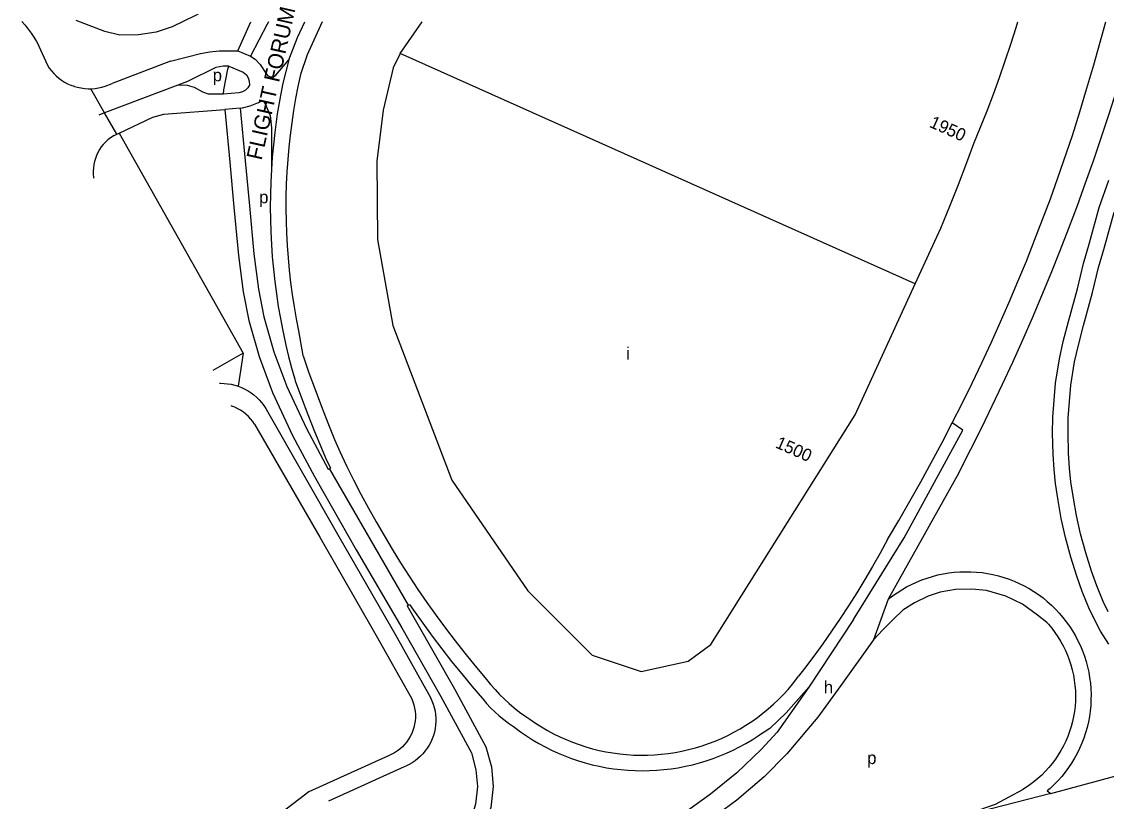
# Model space of a CAD drawing. Extents: x 154765 to 156627, y 383996 to 386132.
# Drawn here: x 155637.8 to 155986.3, y 384249.3 to 384500 of the extents above; entities that cross this region are included whole.
import ezdxf

# ---------------------------------------------------------------- set-up
doc = ezdxf.new("R2010")
doc.units = 0
for name, color, linetype in [('BLT_Basislijn', 7, 'Continuous'), ('BLT_Bebouwing', 7, 'Continuous'), ('BLT_Centroide', 7, 'Continuous'), ('BLT_Huisnummer', 7, 'Continuous'), ('BLT_Huisnummer_reeks', 7, 'Continuous'), ('BLT_Onderverdeling_panden', 7, 'Continuous'), ('BLT_Straatnaam', 7, 'Continuous'), ('BLT_Vlakafsluiter', 7, 'Continuous')]:
    doc.layers.add(name, color=color, linetype=linetype)

msp = doc.modelspace()

# ---------------------------------------------------------------- linework, layer by layer
at = {"layer": 'BLT_Basislijn'}
for p, q in [((155982.27, 384486.09), (155986.13, 384499.98)), ((155643.35, 384492.1), (155646.06, 384486.01)), ((155707.25, 384490.59), (155711.28, 384488.93)), ((155685.59, 384487.29), (155666.85, 384480.09)), ((155980.06, 384478.55), (155982.27, 384486.09)), ((155977.77, 384471.03), (155980.06, 384478.55)), ((155664.46, 384470.64), (155659.99, 384478.42)), ((155708.04, 384472.13), (155703.05, 384471.71)), ((155668.4, 384463.77), (155664.46, 384470.64)), ((155975.44, 384463.36), (155977.77, 384471.03)), ((155667.56, 384463.42), (155668.4, 384463.77)), ((155668.4, 384463.77), (155669.14, 384464.08)), ((155708.93, 384393.37), (155699.2, 384387.82)), ((155716.76, 384374.68), (155739.69, 384334.47)), ((155712.63, 384370.54), (155733.64, 384334.24)), ((155736.23, 384356.1), (155736.99, 384356.46)), ((155736.61, 384356.28), (155762, 384312.37)), ((155938.74, 384354.75), (155916.19, 384314.26)), ((155733.64, 384334.24), (155751.74, 384302.65)), ((155739.69, 384334.47), (155757.87, 384302.8)), ((155761.61, 384312.12), (155762.39, 384312.61)), ((155905.08, 384307.74), (155890.71, 384285.95)), ((155751.74, 384302.65), (155762.65, 384283.24)), ((155757.87, 384302.8), (155769.16, 384282.63)), ((155890.71, 384285.95), (155880.57, 384271.55)), ((155968.5, 384251.86), (156049.38, 384273.6)), ((155760.67, 384260.41), (155736.36, 384249.3)), ((155967.32, 384252.64), (155968.5, 384251.86))]:
    msp.add_line(p, q, dxfattribs=at)
for points in [[(155734.71, 384537.35), (155704.01, 384507.98), (155693.62, 384502.02), (155686.13, 384498.37), (155680.99, 384496.61), (155675.34, 384495.78), (155669.38, 384495.69), (155664.51, 384496.83), (155655.33, 384500.35)], [(155637.8, 384500), (155638.88, 384498.82), (155639.9, 384497.59), (155640.85, 384496.3), (155641.74, 384494.98), (155642.55, 384493.61), (155643.3, 384492.2), (155643.35, 384492.1)], [(155707.25, 384490.59), (155711.4, 384499.98)], [(155717.15, 384499.98), (155716.64, 384499.15)], [(155734.36, 384499.98), (155729.52, 384489.29), (155727.39, 384483.04), (155726.56, 384479.17), (155725.82, 384475.28), (155725.15, 384471.38), (155724.56, 384467.46), (155724.06, 384463.54), (155723.63, 384459.6), (155723.28, 384455.66), (155723.01, 384451.71), (155722.82, 384447.75), (155722.71, 384443.8), (155722.68, 384439.84), (155722.73, 384435.88), (155722.86, 384431.93), (155723.07, 384427.97), (155723.37, 384424.03), (155723.74, 384420.08), (155724.18, 384416.15), (155724.71, 384412.23), (155725.32, 384408.32), (155726.01, 384404.42), (155726.76, 384400.6)], [(155723.64, 384487.72), (155726.46, 384494.94), (155728.74, 384499.98)], [(155716.64, 384499.15), (155711.28, 384488.93)], [(155685.59, 384487.29), (155695.27, 384489.76), (155698.22, 384490.32), (155701.2, 384490.61), (155707.25, 384490.59)], [(155711.28, 384488.93), (155712.79, 384487.96), (155714.46, 384486.26), (155716.25, 384483.38), (155716.86, 384482.61), (155717.71, 384482.23), (155718.67, 384482.25), (155719.5, 384482.77), (155723.64, 384487.72)], [(155646.06, 384486.01), (155646.67, 384485.08), (155647.34, 384484.18), (155648.08, 384483.34), (155648.87, 384482.56), (155649.72, 384481.83), (155650.62, 384481.17), (155651.57, 384480.57), (155652.55, 384480.04), (155653.57, 384479.58), (155654.62, 384479.2), (155654.76, 384479.16)], [(155704.32, 384485.64), (155702.56, 384485.64), (155700.22, 384485.22), (155691.03, 384480.73), (155687.97, 384479.57)], [(155702.64, 384476.69), (155702.72, 384478.11), (155704.07, 384484.72), (155704.32, 384485.64)], [(155704.32, 384485.64), (155708.97, 384483.72), (155710, 384482.85), (155710.54, 384481.97), (155710.94, 384480.81), (155710.96, 384479.55), (155710.49, 384478.71), (155709.67, 384477.92), (155708.7, 384477.39), (155707.62, 384477.11), (155702.64, 384476.69)], [(155723.64, 384487.72), (155721.67, 384480.21), (155720.92, 384476.27), (155719.9, 384470.37), (155719.9, 384470.37), (155719.12, 384464.38), (155718.68, 384460.4), (155718.32, 384456.4), (155718.04, 384452.4)], [(155654.76, 384479.16), (155655.7, 384478.89), (155656.79, 384478.66), (155658.06, 384478.48)], [(155658.06, 384478.48), (155659.14, 384478.42), (155659.99, 384478.42)], [(155659.99, 384478.42), (155660.26, 384478.42), (155661.37, 384478.51), (155662.48, 384478.68), (155663.57, 384478.93), (155664.64, 384479.25), (155666.85, 384480.09)], [(155687.97, 384479.57), (155664.46, 384470.64)], [(155702.64, 384476.69), (155697.81, 384476.69), (155696.01, 384477.31), (155693.32, 384478.82), (155691.1, 384479.48), (155687.97, 384479.57)], [(155989.75, 384478.59), (155989.44, 384477.6), (155987.08, 384470.19), (155984.64, 384462.8), (155982.12, 384455.43), (155979.53, 384448.1), (155976.87, 384440.79), (155974.13, 384433.51), (155971.31, 384426.25), (155968.42, 384419.03), (155965.46, 384411.84), (155962.42, 384404.67), (155959.31, 384397.54), (155956.12, 384390.44), (155952.86, 384383.37), (155949.53, 384376.34), (155946.13, 384369.34), (155942.66, 384362.38), (155939.11, 384355.46), (155938.74, 384354.75)], [(155669.14, 384464.08), (155679.93, 384469.31), (155683.45, 384470.24), (155703.05, 384471.71)], [(155703.05, 384471.71), (155704.65, 384454.77), (155706.01, 384440.35), (155707.47, 384424.81), (155708.96, 384413.13), (155710.77, 384403.94), (155714.1, 384392.31), (155718.36, 384380.76), (155724.85, 384366.97), (155731.84, 384353.7), (155745.31, 384330.12), (155759.92, 384305.12), (155772.44, 384283.05), (155782.28, 384264.93), (155783.76, 384259.45), (155784.28, 384254.07), (155783.61, 384248.39), (155782, 384243.15), (155779.4, 384238.16), (155775.96, 384233.98)], [(155708.04, 384472.13), (155708.8, 384472.29), (155711.22, 384472.91), (155713.9, 384474.03), (155714.79, 384474.52), (155715.16, 384474.58), (155715.47, 384474.37), (155716.05, 384473.56), (155717.66, 384469.83), (155718.06, 384465.81), (155718.04, 384452.4)], [(155708.04, 384472.13), (155709.63, 384455.24), (155710.98, 384440.81), (155712.44, 384425.36), (155713.9, 384413.93), (155715.63, 384405.12), (155718.86, 384393.87), (155722.98, 384382.69), (155729.32, 384369.2), (155736.23, 384356.1)], [(155664.46, 384470.64), (155662.62, 384469.94)], [(155667.56, 384463.42), (155666.32, 384462.59), (155665.5, 384461.95), (155664.74, 384461.25), (155664.03, 384460.49), (155663.39, 384459.69), (155662.81, 384458.83), (155662.29, 384457.93), (155661.85, 384457), (155661.48, 384456.03), (155661.19, 384455.04), (155660.98, 384454.03), (155660.84, 384453), (155660.78, 384451.97), (155660.8, 384450.93), (155660.91, 384449.9), (155660.95, 384449.69)], [(155669.14, 384464.08), (155708.93, 384393.37)], [(155951.88, 384402.48), (155955.09, 384409.83), (155957.88, 384416.41), (155960.6, 384423.03), (155963.25, 384429.68), (155965.82, 384436.36), (155968.31, 384443.07), (155970.74, 384449.8), (155975.44, 384463.36)], [(155718.04, 384452.4), (155717.84, 384448.4), (155717.72, 384444.39), (155717.68, 384440.39), (155717.72, 384436.38), (155717.84, 384432.37), (155718.04, 384428.37), (155718.32, 384424.37), (155718.68, 384420.38), (155719.12, 384416.39), (155719.64, 384412.42), (155720.23, 384408.45), (155720.91, 384404.5), (155721.67, 384400.57), (155721.87, 384399.59)], [(155987.05, 384299.82), (155984.45, 384304.02), (155982.42, 384307.99), (155980.7, 384311.46), (155978.53, 384316.79), (155976.77, 384321.7), (155974.88, 384327.81), (155973.16, 384334.12), (155971.83, 384340.19), (155970.77, 384345.97), (155969.97, 384351.45), (155969.51, 384356.04), (155969.16, 384360.95), (155968.99, 384367.62), (155969.06, 384372.77), (155969.48, 384378.31), (155969.97, 384383.75), (155971.19, 384391.57), (155972.46, 384397.18), (155974.11, 384403.6), (155976.98, 384414.12), (155978.98, 384422.23), (155980.88, 384428.86), (155984.03, 384440.25), (155987.05, 384449.02)], [(155986.88, 384310.24), (155985.26, 384313.52), (155983.2, 384318.58), (155981.52, 384323.29), (155979.68, 384329.2), (155978.02, 384335.31), (155976.73, 384341.17), (155975.71, 384346.79), (155974.93, 384352.06), (155974.49, 384356.47), (155974.16, 384361.2), (155973.99, 384367.65), (155974.05, 384372.55), (155974.46, 384377.9), (155974.93, 384383.14), (155976.11, 384390.63), (155977.32, 384396.01), (155978.94, 384402.32), (155981.82, 384412.87), (155983.81, 384420.94), (155985.69, 384427.5), (155988.81, 384438.77)], [(155936.8, 384370.99), (155940.03, 384377.38), (155943.18, 384383.8), (155946.27, 384390.25), (155949.28, 384396.74), (155951.88, 384402.48)], [(155721.87, 384399.59), (155722.67, 384395.93), (155723.55, 384392.29), (155724.5, 384388.67), (155725.54, 384385.07), (155725.71, 384384.5)], [(155726.76, 384400.6), (155728.18, 384392.69), (155728.22, 384392.49)], [(155728.22, 384392.49), (155730.1, 384387.07), (155732.05, 384381.67), (155734.08, 384376.3), (155736.18, 384370.96), (155738.35, 384365.65), (155739.98, 384361.82)], [(155725.71, 384384.5), (155727.69, 384379.05), (155729.76, 384373.63), (155731.89, 384368.24), (155734.1, 384362.87), (155735.45, 384359.7)], [(155701.4, 384383.71), (155701.65, 384383.72), (155702.82, 384383.69), (155703.98, 384383.58), (155705.12, 384383.39), (155706.26, 384383.12), (155707.4, 384382.77)], [(155707.4, 384382.77), (155708.45, 384382.35), (155709.5, 384381.85), (155710.52, 384381.29), (155711.49, 384380.65), (155712.43, 384379.95), (155713.3, 384379.19), (155714.13, 384378.37), (155714.89, 384377.49), (155715.6, 384376.57), (155716.24, 384375.59), (155716.76, 384374.68)], [(155712.63, 384370.54), (155712.03, 384371.42), (155711.36, 384372.25), (155710.64, 384373.04), (155709.86, 384373.76), (155709.03, 384374.42), (155708.15, 384375.02), (155707.22, 384375.55), (155706.26, 384376.01), (155705.27, 384376.4), (155705.14, 384376.44)], [(155915.95, 384333.46), (155919.6, 384339.62), (155923.18, 384345.82), (155926.69, 384352.05), (155930.13, 384358.33), (155933.5, 384364.64), (155936.8, 384370.99)], [(155905.08, 384307.74), (155921.34, 384334.02), (155940.16, 384368.63)], [(155739.98, 384361.82), (155742.18, 384357.21), (155744.45, 384352.64), (155746.79, 384348.1), (155749.2, 384343.6), (155751.68, 384339.15), (155754.24, 384334.73), (155756.86, 384330.35), (155759.55, 384326.01), (155762.3, 384321.71), (155765.13, 384317.46), (155768.02, 384313.25), (155770.97, 384309.09), (155773.99, 384304.98), (155777.08, 384300.91), (155780.23, 384296.9), (155783.44, 384292.93), (155786.71, 384289.01), (155787.14, 384288.5)], [(155735.45, 384359.7), (155736.99, 384356.46)], [(155915.95, 384333.46), (155913.59, 384329.13), (155911.17, 384324.84), (155908.68, 384320.58), (155906.12, 384316.37), (155903.49, 384312.19), (155900.79, 384308.07), (155898.03, 384303.98), (155895.2, 384299.94), (155892.3, 384295.95), (155889.35, 384292), (155887.42, 384289.51)], [(155916.19, 384314.26), (155917.6, 384315.35), (155919.07, 384316.38), (155920.58, 384317.34), (155922.13, 384318.23), (155923.72, 384319.05), (155925.34, 384319.81), (155927, 384320.48), (155928.68, 384321.09), (155930.39, 384321.61), (155932.12, 384322.07), (155933.88, 384322.44), (155935.64, 384322.73), (155937.42, 384322.95), (155939.2, 384323.08), (155940.99, 384323.14), (155942.78, 384323.11), (155944.57, 384323.01), (155946.35, 384322.82), (155948.12, 384322.56), (155949.87, 384322.22), (155951.61, 384321.8), (155953.33, 384321.3), (155955.03, 384320.73), (155956.7, 384320.08), (155958.33, 384319.35), (155959.93, 384318.56), (155961.5, 384317.69), (155963.03, 384316.75), (155964.51, 384315.75), (155965.95, 384314.68), (155967.33, 384313.55), (155968.67, 384312.36), (155969.95, 384311.11), (155971.17, 384309.8), (155972.33, 384308.44), (155973.43, 384307.03), (155974.47, 384305.57), (155975.44, 384304.07), (155976.35, 384302.53), (155977.18, 384300.94), (155977.94, 384299.32), (155978.63, 384297.67), (155979.24, 384295.99), (155979.78, 384294.28), (155980.24, 384292.55), (155980.63, 384290.81), (155980.93, 384289.04), (155981.16, 384287.27), (155981.3, 384285.48), (155981.37, 384283.7), (155981.36, 384281.91), (155981.27, 384280.12), (155981.09, 384278.34), (155980.84, 384276.57), (155980.51, 384274.81), (155980.1, 384273.06), (155979.61, 384271.34), (155979.05, 384269.64), (155978.41, 384267.97), (155977.7, 384266.33), (155976.91, 384264.72), (155976.05, 384263.15), (155975.13, 384261.62), (155974.14, 384260.13), (155973.08, 384258.69), (155971.95, 384257.29), (155970.77, 384255.95), (155969.53, 384254.66), (155968.23, 384253.43), (155967.32, 384252.64)], [(155967.16, 384306.77), (155964.19, 384309.15), (155959.36, 384312.71), (155954.02, 384315.26), (155947.79, 384317.04), (155943.08, 384317.55), (155937.87, 384317.42), (155932.91, 384316.53), (155929.09, 384315.26), (155924.64, 384313.09), (155920.96, 384310.8), (155917.78, 384307.75), (155914.47, 384304.44), (155911.43, 384301.27)], [(155761.61, 384312.12), (155764.25, 384307.61), (155776.81, 384285.47), (155786.95, 384266.8), (155788.7, 384260.35), (155789.31, 384254.02), (155788.52, 384247.35), (155786.64, 384241.25), (155783.6, 384235.39), (155779.52, 384230.44)], [(155762.39, 384312.61), (155763.67, 384310.74), (155766.64, 384306.55), (155769.68, 384302.4), (155772.78, 384298.3), (155775.95, 384294.24), (155779.17, 384290.24), (155782.46, 384286.29), (155785.82, 384282.38), (155785.94, 384282.24)], [(155967.16, 384306.77), (155967.66, 384306.23), (155968.73, 384304.94), (155969.75, 384303.61), (155970.69, 384302.23), (155971.57, 384300.8), (155972.39, 384299.34), (155973.13, 384297.84), (155973.79, 384296.3), (155974.39, 384294.74), (155974.9, 384293.15), (155975.35, 384291.53), (155975.71, 384289.9), (155976, 384288.25), (155976.2, 384286.59), (155976.33, 384284.92), (155976.38, 384283.24), (155976.34, 384281.57), (155976.23, 384279.9), (155976.04, 384278.23), (155975.77, 384276.58), (155975.42, 384274.95), (155974.99, 384273.33), (155974.48, 384271.73), (155973.9, 384270.16), (155973.25, 384268.62), (155972.52, 384267.11), (155971.72, 384265.64), (155970.85, 384264.21), (155969.92, 384262.82), (155968.91, 384261.48), (155967.85, 384260.19), (155966.73, 384258.95), (155965.54, 384257.76), (155964.3, 384256.63), (155963.02, 384255.57), (155961.68, 384254.56), (155960.29, 384253.62), (155959.45, 384253.1)], [(155911.43, 384301.27), (155901.03, 384286.49), (155893.59, 384276.4), (155883.66, 384264.54)], [(155787.14, 384288.5), (155788.48, 384286.84), (155789.89, 384285.23), (155791.35, 384283.67), (155792.88, 384282.16), (155794.45, 384280.72), (155796.08, 384279.33), (155797.76, 384278.01), (155799.49, 384276.75), (155801.07, 384275.68)], [(155801.07, 384275.68), (155802.91, 384274.42), (155804.8, 384273.22), (155806.72, 384272.09), (155808.69, 384271.04), (155810.69, 384270.05), (155812.73, 384269.13), (155814.8, 384268.29), (155816.9, 384267.53), (155819.02, 384266.84), (155821.17, 384266.22), (155823.33, 384265.68), (155825.52, 384265.23), (155827.72, 384264.85), (155829.93, 384264.55), (155832.15, 384264.32), (155834.38, 384264.18), (155836.61, 384264.12), (155838.84, 384264.14), (155841.07, 384264.24), (155843.3, 384264.41), (155845.52, 384264.67), (155847.72, 384265.01), (155849.92, 384265.42), (155852.09, 384265.92), (155854.25, 384266.49), (155856.39, 384267.14), (155858.5, 384267.86), (155860.59, 384268.66), (155862.64, 384269.53), (155864.66, 384270.48), (155866.65, 384271.5), (155868.6, 384272.59), (155870.51, 384273.75), (155872.37, 384274.97), (155874.19, 384276.26), (155875.96, 384277.62), (155877.69, 384279.04), (155879.36, 384280.52), (155880.98, 384282.06), (155882.54, 384283.65), (155884.04, 384285.3), (155885.49, 384287.01), (155886.87, 384288.76), (155887.42, 384289.51)], [(155890.71, 384285.95), (155883.37, 384277.8), (155878.14, 384272.71), (155874.5, 384270.38)], [(155762.65, 384283.24), (155763.12, 384282.3), (155763.51, 384281.32), (155763.82, 384280.32), (155764.06, 384279.3), (155764.22, 384278.26), (155764.3, 384277.22), (155764.3, 384276.17), (155764.21, 384275.12), (155764.05, 384274.09), (155763.82, 384273.07), (155763.5, 384272.07), (155763.11, 384271.09), (155762.64, 384270.15), (155762.11, 384269.25), (155761.51, 384268.39), (155760.84, 384267.58), (155760.12, 384266.82), (155759.34, 384266.12), (155758.51, 384265.48), (155757.63, 384264.91), (155756.71, 384264.41), (155755.85, 384264.01)], [(155769.16, 384282.63), (155769.63, 384281.59), (155770.03, 384280.53), (155770.35, 384279.44), (155770.6, 384278.33), (155770.76, 384277.21), (155770.85, 384276.08), (155770.86, 384274.94), (155770.78, 384273.81), (155770.63, 384272.68), (155770.4, 384271.57), (155770.09, 384270.48), (155769.7, 384269.41), (155769.24, 384268.37), (155768.71, 384267.37), (155768.11, 384266.4), (155767.45, 384265.48), (155766.72, 384264.61), (155765.93, 384263.8), (155765.08, 384263.04), (155764.18, 384262.34), (155763.24, 384261.71), (155762.26, 384261.14), (155761.23, 384260.65), (155760.67, 384260.41)], [(155785.94, 384282.24), (155787.18, 384280.8), (155788.48, 384279.41), (155789.83, 384278.08), (155791.24, 384276.8), (155792.7, 384275.59), (155794.21, 384274.43), (155795.77, 384273.35), (155796.23, 384273.05)], [(155796.23, 384273.05), (155798.08, 384271.67), (155799.99, 384270.36), (155801.95, 384269.1), (155803.94, 384267.92), (155805.98, 384266.81), (155808.05, 384265.77), (155810.16, 384264.8), (155812.3, 384263.9), (155814.47, 384263.08), (155816.67, 384262.33), (155818.89, 384261.66), (155821.13, 384261.07), (155823.39, 384260.55), (155825.67, 384260.11), (155827.96, 384259.76), (155830.27, 384259.48), (155832.58, 384259.28), (155834.9, 384259.16), (155837.22, 384259.12), (155839.54, 384259.16), (155841.86, 384259.28), (155844.17, 384259.48), (155846.47, 384259.75), (155848.76, 384260.11), (155851.04, 384260.55), (155853.3, 384261.06), (155855.55, 384261.66), (155857.77, 384262.33), (155859.97, 384263.07), (155862.14, 384263.9), (155864.28, 384264.79), (155866.39, 384265.76), (155868.46, 384266.8), (155870.5, 384267.91), (155872.49, 384269.09), (155874.45, 384270.34), (155874.5, 384270.38)], [(155880.57, 384271.55), (155875.35, 384265.99), (155867.6, 384258.51), (155859.16, 384251.55), (155849.87, 384244.94), (155838.55, 384237.95), (155824.89, 384231.23), (155814.41, 384227.03), (155805.76, 384224.34), (155795.71, 384221.73)], [(155755.85, 384264.01), (155730.1, 384252.3), (155721.76, 384246.02)], [(155883.66, 384264.54), (155876.37, 384257.21), (155867.57, 384249.7), (155857.42, 384242.15), (155848.96, 384236.9), (155841.08, 384232.67), (155831.46, 384228.24), (155823.11, 384225.18), (155816.36, 384222.9), (155808.84, 384220.52), (155800.62, 384218.26)], [(155937.99, 384244.01), (155950.63, 384248.43), (155959.45, 384253.1)]]:
    msp.add_lwpolyline(points, dxfattribs=at)
at = {"layer": 'BLT_Bebouwing'}
for points in [[(155759.36, 384489.73), (155766.48, 384499.98)], [(155943.75, 384460.77), (155945.9, 384466.03), (155947.99, 384471.31), (155949.99, 384476.63), (155951.93, 384481.98), (155953.78, 384487.35), (155955.56, 384492.74), (155957.27, 384498.16), (155957.82, 384499.98)], [(155759.36, 384489.73), (155757.13, 384485.19), (155753.92, 384471.54), (155751.94, 384455.13), (155752.16, 384429.95), (155757.02, 384402.25), (155775.99, 384352.61), (155800.41, 384316.93), (155821.08, 384296.25), (155836.86, 384291), (155851.89, 384294.33), (155859.26, 384299.7), (155905.56, 384373.61), (155924.86, 384415.73)], [(155924.86, 384415.73), (155933.08, 384433.6), (155935.96, 384440.62), (155938.76, 384447.67), (155941.49, 384454.75), (155943.75, 384460.77)]]:
    msp.add_lwpolyline(points, dxfattribs=at)
at = {"layer": 'BLT_Onderverdeling_panden'}
msp.add_lwpolyline([(155924.86, 384415.73), (155759.36, 384489.73)], dxfattribs=at)
at = {"layer": 'BLT_Vlakafsluiter'}
for p, q in [((155708.93, 384393.37), (155707.4, 384382.77)), ((155940.16, 384368.63), (155936.8, 384370.99)), ((155916.19, 384314.26), (155911.43, 384301.27)), ((155968.5, 384251.86), (155937.99, 384244.01))]:
    msp.add_line(p, q, dxfattribs=at)

# ---------------------------------------------------------------- texts
at = {"layer": 'BLT_Centroide'}
for s, p in [('p', (155699.18, 384480.8)), ('p', (155714.1, 384441.59)), ('i', (155832.02, 384391.31)), ('h', (155895.52, 384283.97)), ('p', (155909.46, 384261.28))]:
    msp.add_text(s, height=4, dxfattribs=at).set_placement(p)
at = {"layer": 'BLT_Huisnummer'}
msp.add_text('1500', height=4, rotation=335.9062, dxfattribs=at).set_placement((155879.67, 384363.17))
at = {"layer": 'BLT_Huisnummer_reeks'}
msp.add_text('1950', height=4, rotation=335.9062, dxfattribs=at).set_placement((155929.16, 384466.23))
at = {"layer": 'BLT_Straatnaam'}
msp.add_text('FLIGHT FORUM', height=5, rotation=77.3725, dxfattribs=at).set_placement((155714.85, 384455.22))

doc.saveas('drawing.dxf')
